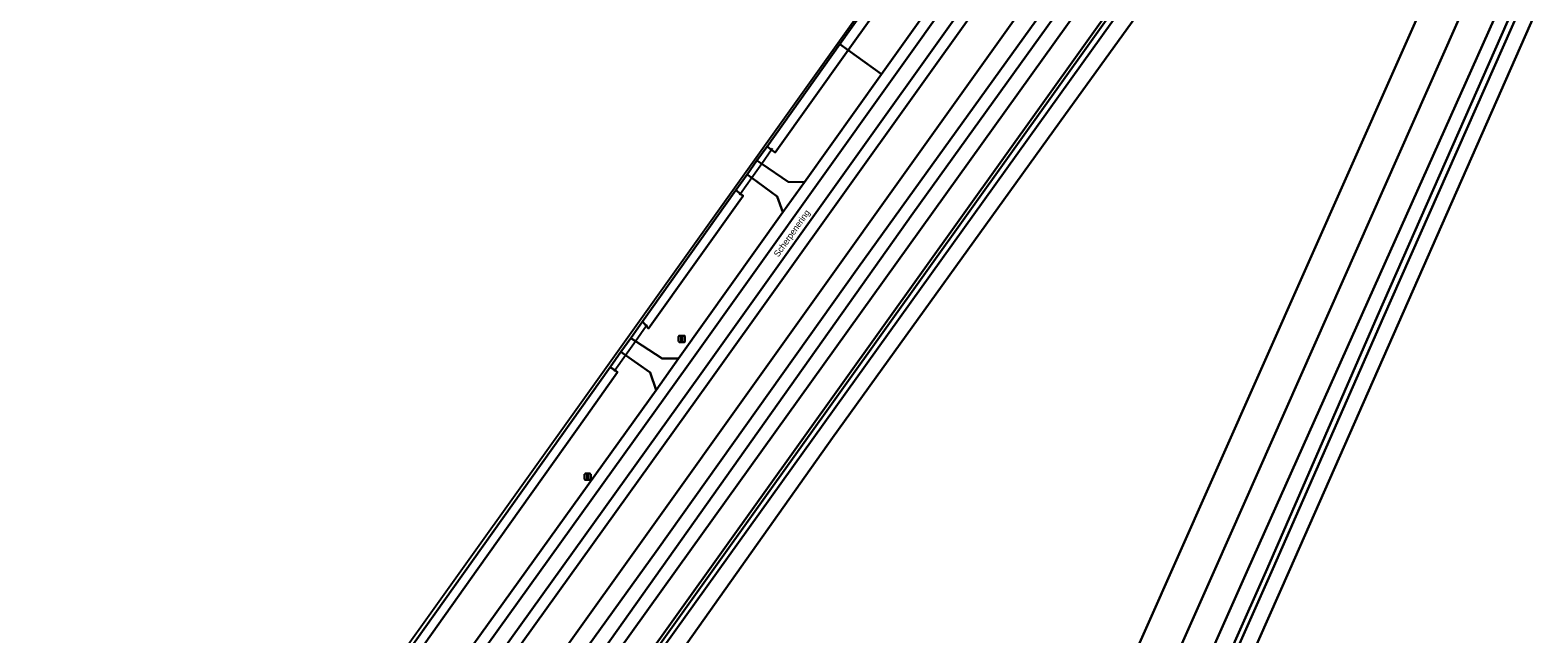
# Model space of a CAD drawing. Extents: x 152881 to 155736, y 382924 to 386919.
# Drawn here: x 152912.4 to 153150, y 383489.7 to 383584.8 of the extents above; entities that cross this region are included whole.
import ezdxf

# ---------------------------------------------------------------- set-up
doc = ezdxf.new("R2010")
doc.units = 0
for name, color, linetype in [('IMGEO_Bouwland', 7, 'Continuous'), ('IMGEO_Duiker', 7, 'Continuous'), ('IMGEO_Greppel_droge_sloot', 7, 'Continuous'), ('IMGEO_Groenvoorziening', 7, 'Continuous'), ('IMGEO_Hek', 7, 'Continuous'), ('IMGEO_Lichtmast', 7, 'Continuous'), ('IMGEO_Oever', 7, 'Continuous'), ('IMGEO_Openbare_ruimte_label', 7, 'Continuous'), ('IMGEO_Rijbaan_lokaal_gesloten', 7, 'Continuous'), ('IMGEO_Rijbaan_lokaal_halfverhard', 7, 'Continuous'), ('IMGEO_Rijbaan_lokaal_open', 7, 'Continuous'), ('IMGEO_Terreindeel_onvherhard', 7, 'Continuous'), ('IMGEO_Verkeersbordpaal', 7, 'Continuous'), ('IMGEO_Waterloop', 7, 'Continuous')]:
    doc.layers.add(name, color=color, linetype=linetype)

msp = doc.modelspace()

# ---------------------------------------------------------------- linework, layer by layer
at = {"layer": 'IMGEO_Bouwland'}
for points in [[(152953.05, 383460.39), (152953.07, 383460.41), (153003.78, 383531.73), (153005.51, 383534.16), (153007.05, 383536.33), (153008.89, 383538.92), (153023.63, 383559.65), (153025.37, 383562.1), (153026.93, 383564.3), (153028.52, 383566.52), (153039.97, 383582.62), (153081, 383640.33), (153109.22, 383679.89), (153110.57, 383681.77), (153112.26, 383684.15), (153115.92, 383689.28), (153121.16, 383696.77)], [(153110.49, 383681.83), (153000, 383527.25), (152980.52, 383500), (152951.85, 383459.88), (152948.58, 383455.56), (152943.31, 383447.72), (152938.52, 383439.65), (152933.32, 383430.26), (152927.89, 383419.76), (152923.79, 383410.58), (152920.24, 383401.77), (152916.91, 383392.35), (152914.15, 383383.67), (152912.42, 383377.32), (152913.14, 383377.16), (152914.31, 383381.97), (152916.96, 383389.41), (152917.91, 383392.06), (152918.91, 383394.87), (152919.56, 383396.68), (152920.4, 383399.03), (152930.98, 383424.43), (152930.99, 383424.44)]]:
    msp.add_lwpolyline(points, dxfattribs=at)
at = {"layer": 'IMGEO_Duiker'}
for points in [[(153029.37, 383566.18), (153029.24, 383565.99), (153027.68, 383563.79), (153026.11, 383561.56), (153024.35, 383559.06), (153024.19, 383558.83)], [(153004.46, 383531.12), (153004.55, 383531.25), (153006.24, 383533.64), (153007.8, 383535.84), (153009.5, 383538.25), (153009.65, 383538.47)]]:
    msp.add_lwpolyline(points, dxfattribs=at)
at = {"layer": 'IMGEO_Greppel_droge_sloot'}
for points in [[(153110.72, 383678.68), (153110.05, 383679.22), (153109.22, 383679.89), (153081, 383640.33), (153039.97, 383582.62), (153041.31, 383581.66)], [(153041.31, 383581.66), (153039.97, 383582.62), (153028.52, 383566.52), (153029.24, 383565.99), (153029.8, 383565.58)], [(153024.77, 383558.71), (153024.35, 383559.06), (153023.63, 383559.65), (153008.89, 383538.92), (153009.5, 383538.25), (153009.86, 383537.85)]]:
    msp.add_lwpolyline(points, close=True, dxfattribs=at)
for points in [[(152982.98, 383500), (153000, 383523.99), (153004.96, 383530.98), (153004.55, 383531.25), (153003.78, 383531.73), (152953.07, 383460.41), (152953.05, 383460.39)], [(152954.9, 383460.42), (152982.98, 383500)]]:
    msp.add_lwpolyline(points, dxfattribs=at)
at = {"layer": 'IMGEO_Groenvoorziening'}
for points in [[(153270.96, 383020.95), (153273.9, 383025.38), (153273.81, 383025.44), (153273.05, 383025.91), (153030.73, 383178.33), (152959.64, 383223.14), (152933.46, 383239.65), (152928.97, 383247.39), (152928.17, 383250), (152926.53, 383255.4), (152926.3, 383256.13), (152927.9, 383267.67), (152937.99, 383340.71), (152944.2, 383369.81), (152955.53, 383400.99), (152969.74, 383429.27), (152974.63, 383436.64), (152983.1, 383449.09), (153167.02, 383706.28)], [(153167.48, 383706.07), (153020.12, 383500), (153000, 383471.86), (152991.73, 383460.27), (152984.57, 383450.28), (152980.95, 383445.04), (152975.54, 383437.07), (152970.18, 383429.01), (152956, 383400.83), (152944.68, 383369.67), (152938.49, 383340.64), (152937.43, 383333.04), (152926.7, 383256.55)], [(152915.54, 383256.39), (152924.69, 383331.98), (152925.5, 383338.71), (152926.95, 383347.68), (152928.68, 383356.6), (152933.15, 383374.68), (152938.97, 383392.38), (152945.87, 383408.73), (152954.05, 383424.48), (152964, 383441.08), (152974.97, 383457.01), (153000, 383492.04), (153005.69, 383500), (153056.34, 383570.88), (153149.88, 383701.78)], [(153140.83, 383699.39), (153083.61, 383619.34), (153019.41, 383529.42), (152967.99, 383457.78), (152964.26, 383452.59)], [(153166.34, 383697.41), (153074.59, 383570.26), (153038.85, 383520.59), (153005.86, 383474.07), (152998.15, 383463.45), (152990.65, 383452.69), (152983.35, 383441.79), (152976.26, 383430.75), (152971.61, 383422.45), (152967.23, 383414.01), (152963.14, 383405.42), (152959.32, 383396.71), (152955.8, 383387.89), (152948.09, 383365.28), (152946.56, 383359.86), (152945.28, 383354.38), (152944.28, 383348.84), (152943.55, 383343.26), (152934.49, 383277.01)], [(153154.54, 383695.43), (153014.38, 383500), (153000, 383479.96), (152979.1, 383450.82), (152968.8, 383436), (152960.1, 383420.18), (152956.58, 383412.98), (152946.23, 383389.36), (152943.15, 383380.58), (152940.47, 383371.66), (152936.07, 383354.37), (152932.92, 383336.8), (152922.23, 383258.87), (152921.88, 383254.58)], [(152996.45, 383283.74), (153006.43, 383306.24), (153011.2, 383316.98), (153012.03, 383318.84), (153017.47, 383331.11), (153092.42, 383500), (153176.63, 383689.68)], [(153155, 383599.9), (153110.95, 383500), (153037.4, 383334.02), (153003.42, 383259.85)], [(152930.08, 383265.6), (152940.85, 383343.79), (152941.6, 383349.47), (152942.63, 383355.11), (152943.92, 383360.7), (152945.47, 383366.22), (152948.34, 383375.26), (152951.48, 383384.21), (152954.88, 383393.07), (152958.53, 383401.83), (152962.44, 383410.47), (152966.79, 383419.18), (152971.42, 383427.75), (152976.33, 383436.16), (152981.51, 383444.4), (152986.97, 383452.47), (153089.76, 383595.8)], [(153011.06, 383528.14), (153010.1, 383530.89), (153006.24, 383533.64), (153005.51, 383534.16), (153003.78, 383531.73), (153004.55, 383531.25), (153004.96, 383530.98), (153000, 383523.99), (152982.98, 383500), (152954.9, 383460.42)], [(152959.33, 383456.18), (152963.01, 383461.3), (153011.06, 383528.14)]]:
    msp.add_lwpolyline(points, dxfattribs=at)
for points in [[(153116.62, 383675.93), (153116.51, 383676.19), (153115.6, 383678.37), (153111.44, 383681.18), (153110.57, 383681.77), (153109.22, 383679.89), (153110.05, 383679.22), (153110.72, 383678.68), (153041.31, 383581.66), (153046.56, 383577.9), (153078.72, 383622.96)], [(153150.45, 383615.74), (153099.12, 383500), (153032.94, 383351.11), (153004.52, 383287.14), (153019.78, 383308.9), (153032.93, 383339.53), (153104.31, 383500), (153154.22, 383611.49), (153155.86, 383614.47), (153157.7, 383615.77), (153158.68, 383615.12), (153159.65, 383617.03), (153159.09, 383617.27), (153157.38, 383617.84), (153155.61, 383617.92), (153153.87, 383617.63), (153152.63, 383617.18), (153151.49, 383616.55)], [(153046.56, 383577.9), (153041.31, 383581.66), (153029.8, 383565.58), (153029.24, 383565.99), (153028.52, 383566.52), (153026.93, 383564.3), (153027.68, 383563.79), (153031.86, 383560.95), (153034.43, 383560.91)], [(153031.03, 383556.17), (153030.12, 383558.62), (153026.11, 383561.56), (153025.37, 383562.1), (153023.63, 383559.65), (153024.35, 383559.06), (153024.77, 383558.71), (153009.86, 383537.85), (153009.5, 383538.25), (153008.89, 383538.92), (153007.05, 383536.33), (153007.8, 383535.84), (153011.98, 383533.11), (153014.56, 383533.1)]]:
    msp.add_lwpolyline(points, close=True, dxfattribs=at)
at = {"layer": 'IMGEO_Hek'}
msp.add_lwpolyline([(152926.53, 383255.4), (152926.3, 383256.13), (152927.9, 383267.67), (152928.84, 383274.52), (152937.99, 383340.71), (152944.2, 383369.81), (152955.53, 383400.99), (152969.74, 383429.27), (152974.63, 383436.64), (152983.1, 383449.09), (153167.02, 383706.28)], dxfattribs=at)
at = {"layer": 'IMGEO_Lichtmast'}
for p, q in [((152999.76, 383514.09), (152999.76, 383514.89)), ((152999.76, 383514.89), (152999.76, 383514.09)), ((152999.86, 383514.99), (153000.65, 383514.99)), ((153000.65, 383514.99), (152999.86, 383514.99)), ((153000.65, 383513.99), (152999.86, 383513.99)), ((152999.86, 383513.99), (153000.65, 383513.99)), ((153000.75, 383514.89), (153000.75, 383514.09)), ((153000.75, 383514.09), (153000.75, 383514.89))]:
    msp.add_line(p, q, dxfattribs=at)
msp.add_lwpolyline([(153000.18, 383514.87), (153000.33, 383514.87), (153000.33, 383514.12), (153000.18, 383514.12), (153000.18, 383514.87)], dxfattribs=at)
for centre, start, end in [((152999.86, 383514.89), 90, 180), ((152999.86, 383514.89), 90, 180), ((152999.86, 383514.09), 180, 270), ((152999.86, 383514.09), 180, 270), ((153000.65, 383514.89), 0, 90), ((153000.65, 383514.89), 360, 90), ((153000.65, 383514.09), 270, 0), ((153000.65, 383514.09), 270, 0)]:
    msp.add_arc(centre, 0.1, start, end, dxfattribs=at)
at = {"layer": 'IMGEO_Oever'}
for points in [[(153175.28, 383734.56), (153165.35, 383716.76), (153152.97, 383697.34), (153120.26, 383651.98), (153086.38, 383604.46), (153051.51, 383555.94), (152998.74, 383481.58), (152970.73, 383442.73)], [(152968.65, 383443.88), (153011.03, 383502.7), (153042.92, 383547.51), (153084.39, 383605.07), (153125.5, 383662.8), (153153.42, 383702.55), (153163.36, 383717.82)], [(153149.88, 383701.78), (153056.34, 383570.88), (153005.69, 383500), (153000, 383492.04), (152974.97, 383457.01), (152964, 383441.08), (152954.05, 383424.48), (152945.87, 383408.73), (152938.97, 383392.38), (152933.15, 383374.68), (152928.68, 383356.6), (152926.95, 383347.68), (152925.5, 383338.71), (152924.69, 383331.98), (152915.54, 383256.39)], [(152921.88, 383254.58), (152922.23, 383258.87), (152932.92, 383336.8), (152936.07, 383354.37), (152940.47, 383371.66), (152943.15, 383380.58), (152946.23, 383389.36), (152956.58, 383412.98), (152960.1, 383420.18), (152968.8, 383436), (152979.1, 383450.82), (153000, 383479.96), (153014.38, 383500), (153154.54, 383695.43)], [(153154.22, 383611.49), (153104.31, 383500), (153032.93, 383339.53), (153019.78, 383308.9), (153026.41, 383318.36), (153048.75, 383368.41), (153107.29, 383500), (153124.7, 383539.82), (153157, 383612.95)], [(153157.61, 383611.92), (153125.57, 383539.5), (153108.23, 383500), (153049.54, 383368.07), (153029.73, 383323.09), (153037.4, 383334.02), (153110.95, 383500), (153155, 383599.9)]]:
    msp.add_lwpolyline(points, dxfattribs=at)
at = {"layer": 'IMGEO_Rijbaan_lokaal_gesloten'}
for points in [[(153135.62, 383702.48), (153120.01, 383680.66), (153116.62, 383675.93), (153078.72, 383622.96), (153046.56, 383577.9), (153034.43, 383560.91), (153031.03, 383556.17), (153014.56, 383533.1), (153011.06, 383528.14), (152963.01, 383461.3), (152964.52, 383460.23), (153015.87, 383531.82), (153080.07, 383621.72), (153137.24, 383701.72)], [(153137.24, 383701.72), (153080.07, 383621.72), (153015.87, 383531.82), (152964.52, 383460.23), (152966.53, 383458.81), (153017.9, 383530.36), (153082.11, 383620.32)], [(153139.27, 383700.36), (153082.11, 383620.32), (153017.9, 383530.36), (152966.53, 383458.81), (152967.99, 383457.78), (153019.41, 383529.42), (153083.61, 383619.34), (153140.83, 383699.39)]]:
    msp.add_lwpolyline(points, dxfattribs=at)
msp.add_lwpolyline([(153176.63, 383689.68), (153092.42, 383500), (153017.47, 383331.11), (153012.03, 383318.84), (153011.2, 383316.98), (153006.43, 383306.24), (152996.45, 383283.74), (152990.58, 383270.5), (152986.72, 383261.75), (153004.52, 383287.14), (153032.94, 383351.11), (153099.12, 383500), (153150.45, 383615.74), (153151.1, 383617.22), (153156.52, 383629.6), (153156.83, 383630.29), (153156.9, 383630.44), (153156.9, 383630.45), (153158.81, 383634.75), (153161.37, 383640.49), (153182.29, 383687.54)], close=True, dxfattribs=at)
at = {"layer": 'IMGEO_Rijbaan_lokaal_halfverhard'}
for points in [[(152934.49, 383277.01), (152943.55, 383343.26), (152944.28, 383348.84), (152945.28, 383354.38), (152946.56, 383359.86), (152948.09, 383365.28), (152955.8, 383387.89), (152959.32, 383396.71), (152963.14, 383405.42), (152967.23, 383414.01), (152971.61, 383422.45), (152976.26, 383430.75), (152983.35, 383441.79), (152990.65, 383452.69), (152998.15, 383463.45), (153005.86, 383474.07), (153038.85, 383520.59), (153074.59, 383570.26), (153166.34, 383697.41)], [(153089.76, 383595.8), (152986.97, 383452.47), (152981.51, 383444.4), (152976.33, 383436.16), (152971.42, 383427.75), (152966.79, 383419.18), (152962.44, 383410.47), (152958.53, 383401.83), (152954.88, 383393.07), (152951.48, 383384.21), (152948.34, 383375.26), (152945.47, 383366.22), (152943.92, 383360.7), (152942.63, 383355.11), (152941.6, 383349.47), (152940.85, 383343.79), (152930.08, 383265.6)]]:
    msp.add_lwpolyline(points, dxfattribs=at)
at = {"layer": 'IMGEO_Rijbaan_lokaal_open'}
for points in [[(153031.86, 383560.95), (153027.68, 383563.79), (153026.93, 383564.3), (153025.37, 383562.1), (153026.11, 383561.56), (153030.12, 383558.62), (153031.03, 383556.17), (153034.43, 383560.91)], [(153014.56, 383533.1), (153011.98, 383533.11), (153007.8, 383535.84), (153007.05, 383536.33), (153005.51, 383534.16), (153006.24, 383533.64), (153010.1, 383530.89), (153011.06, 383528.14)]]:
    msp.add_lwpolyline(points, close=True, dxfattribs=at)
at = {"layer": 'IMGEO_Terreindeel_onvherhard'}
for points in [[(152926.7, 383256.55), (152937.43, 383333.04), (152938.49, 383340.64), (152944.68, 383369.67), (152956, 383400.83), (152970.18, 383429.01), (152975.54, 383437.07), (152980.95, 383445.04), (152984.57, 383450.28), (152991.73, 383460.27), (153000, 383471.86), (153020.12, 383500), (153167.48, 383706.07)], [(153167.02, 383706.28), (152983.1, 383449.09), (152974.63, 383436.64), (152969.74, 383429.27), (152955.53, 383400.99), (152944.2, 383369.81), (152937.99, 383340.71), (152927.9, 383267.67)]]:
    msp.add_lwpolyline(points, dxfattribs=at)
at = {"layer": 'IMGEO_Verkeersbordpaal'}
for p, q in [((153014.59, 383535.79), (153014.59, 383536.59)), ((153014.59, 383536.59), (153014.59, 383535.79)), ((153014.69, 383536.69), (153015.48, 383536.69)), ((153015.48, 383536.69), (153014.69, 383536.69)), ((153015.48, 383535.69), (153014.69, 383535.69)), ((153014.69, 383535.69), (153015.48, 383535.69)), ((153015.58, 383536.59), (153015.58, 383535.79)), ((153015.58, 383535.79), (153015.58, 383536.59))]:
    msp.add_line(p, q, dxfattribs=at)
msp.add_lwpolyline([(153015.01, 383536.56), (153015.16, 383536.56), (153015.16, 383535.81), (153015.01, 383535.81), (153015.01, 383536.56)], dxfattribs=at)
for centre, start, end in [((153014.69, 383536.59), 90, 180), ((153014.69, 383536.59), 90, 180), ((153014.69, 383535.79), 180, 270), ((153014.69, 383535.79), 180, 270), ((153015.48, 383536.59), 0, 90), ((153015.48, 383536.59), 360, 90), ((153015.48, 383535.79), 270, 0), ((153015.48, 383535.79), 270, 0)]:
    msp.add_arc(centre, 0.1, start, end, dxfattribs=at)
at = {"layer": 'IMGEO_Waterloop'}
for points in [[(152970.73, 383442.73), (152998.74, 383481.58), (153051.51, 383555.94), (153086.38, 383604.46), (153120.26, 383651.98), (153152.97, 383697.34), (153165.35, 383716.76), (153175.28, 383734.56)], [(153163.36, 383717.82), (153153.42, 383702.55), (153125.5, 383662.8), (153084.39, 383605.07), (153042.92, 383547.51), (153011.03, 383502.7), (152968.65, 383443.88)]]:
    msp.add_lwpolyline(points, dxfattribs=at)
msp.add_lwpolyline([(153048.75, 383368.41), (153026.41, 383318.36), (153029.73, 383323.09), (153049.54, 383368.07), (153108.23, 383500), (153125.57, 383539.5), (153157.61, 383611.92), (153159.1, 383612.35), (153158.46, 383613.63), (153157, 383612.95), (153124.7, 383539.82), (153107.29, 383500)], close=True, dxfattribs=at)

# ---------------------------------------------------------------- texts
at = {"layer": 'IMGEO_Openbare_ruimte_label'}
msp.add_text('Scherpenering', height=1, rotation=54.4823, dxfattribs=at).set_placement((153030.3, 383549.01))

doc.saveas('drawing.dxf')
